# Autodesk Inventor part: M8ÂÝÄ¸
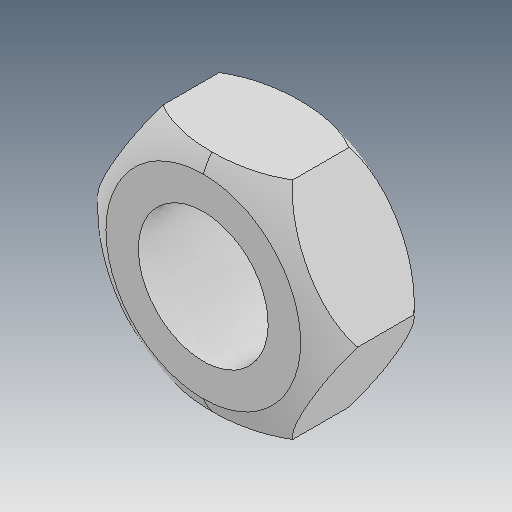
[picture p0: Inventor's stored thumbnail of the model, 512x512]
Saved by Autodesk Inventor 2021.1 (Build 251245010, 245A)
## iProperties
Created: 2019-04
Part Number: M8ÂÝÄ¸
Material: Ogólny
Document SubType Name: Modeling
Designer: user
Density: 1 g/cm^3
Appearance: Domyślna
Author: user
Revision Number: ÈÎºÎ
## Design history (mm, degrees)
feature "ÊäÈë1"
node "Bryła1"
